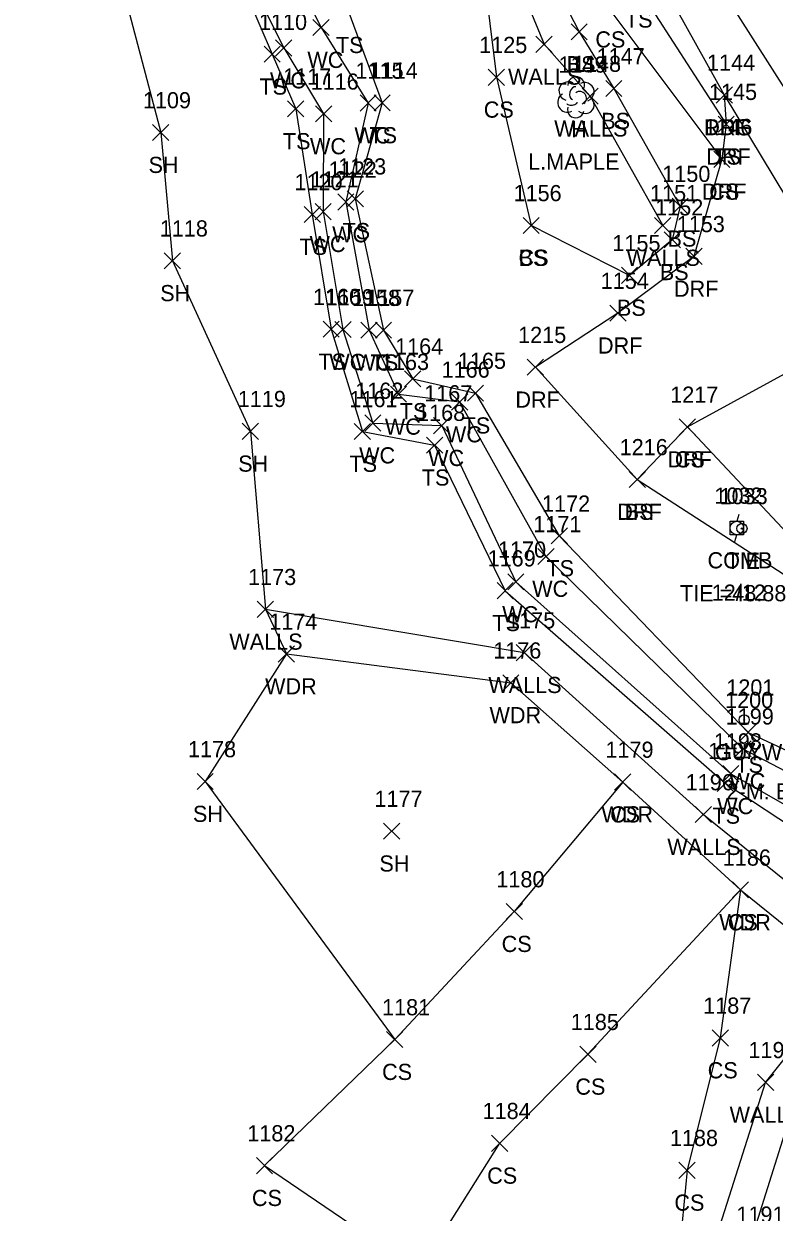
# Model space of a CAD drawing. Extents: x 1441651 to 1442140, y 243798 to 245625.
# Drawn here: x 1441906.3 to 1441999.2, y 245354.1 to 245501.1 of the extents above; entities that cross this region are included whole.
import ezdxf

# ---------------------------------------------------------------- set-up
doc = ezdxf.new("R2010")
doc.units = 0
for name, color, linetype in [('C_A', 7, 'Continuous'), ('C_C', 7, 'Continuous'), ('C_I', 7, 'Continuous'), ('CBP', 7, 'Continuous'), ('L_A', 7, 'Continuous'), ('L_C', 7, 'Continuous'), ('L_I', 7, 'Continuous'), ('L_TIC', 7, 'Continuous'), ('LAWA', 7, 'Continuous'), ('LAWE', 7, 'Continuous'), ('LELB', 7, 'Continuous'), ('LSOGP', 7, 'Continuous'), ('LTD', 7, 'Continuous'), ('LWS', 7, 'Continuous'), ('P_A', 7, 'Continuous'), ('P_I', 7, 'Continuous'), ('P_TIC', 7, 'Continuous'), ('PEU', 7, 'Continuous'), ('PRC', 7, 'Continuous'), ('R_A', 7, 'Continuous'), ('R_I', 7, 'Continuous'), ('R_TIC', 7, 'Continuous'), ('RDF', 7, 'Continuous'), ('U_A', 7, 'Continuous'), ('U_C', 7, 'Continuous'), ('U_I', 7, 'Continuous'), ('UP', 7, 'Continuous'), ('UPGW', 7, 'Continuous')]:
    doc.layers.add(name, color=color, linetype=linetype)

msp = doc.modelspace()

# ---------------------------------------------------------------- linework, layer by layer
at = {"layer": 'CBP'}
for radius in [0.625, 0.0833]:
    msp.add_circle((1441995.18, 245438.67), radius, dxfattribs=at)
at = {"layer": 'L_TIC'}
for points in [[(1441942.11, 245499.64), (1441944.11, 245501.64)], [(1441944.11, 245499.64), (1441942.11, 245501.64)], [(1441974.05, 245499.1), (1441976.05, 245501.1)], [(1441976.05, 245499.1), (1441974.05, 245501.1)], [(1441936.07, 245496.34), (1441938.07, 245498.34)], [(1441938.07, 245496.34), (1441936.07, 245498.34)], [(1441937.49, 245497.11), (1441939.49, 245499.11)], [(1441939.49, 245497.11), (1441937.49, 245499.11)], [(1441969.7, 245497.57), (1441971.7, 245499.57)], [(1441971.7, 245497.57), (1441969.7, 245499.57)], [(1441963.8, 245493.49), (1441965.8, 245495.49)], [(1441965.8, 245493.49), (1441963.8, 245495.49)], [(1441978.33, 245492.09), (1441980.33, 245494.09)], [(1441980.33, 245492.09), (1441978.33, 245494.09)], [(1441947.93, 245490.3), (1441949.93, 245492.3)], [(1441949.93, 245490.3), (1441947.93, 245492.3)], [(1441949.68, 245490.32), (1441951.68, 245492.32)], [(1441951.68, 245490.32), (1441949.68, 245492.32)], [(1441975.4, 245491.16), (1441977.4, 245493.16)], [(1441977.4, 245491.16), (1441975.4, 245493.16)], [(1441938.98, 245489.58), (1441940.98, 245491.58)], [(1441940.98, 245489.58), (1441938.98, 245491.58)], [(1441942.43, 245488.96), (1441944.43, 245490.96)], [(1441944.43, 245488.96), (1441942.43, 245490.96)], [(1441992.22, 245487.68), (1441994.22, 245489.68)], [(1441994.22, 245487.68), (1441992.22, 245489.68)], [(1441922.28, 245486.65), (1441924.28, 245488.65)], [(1441924.28, 245486.65), (1441922.28, 245488.65)], [(1441991.69, 245483.34), (1441993.69, 245485.34)], [(1441993.69, 245483.34), (1441991.69, 245485.34)], [(1441945.18, 245478.07), (1441947.18, 245480.07)], [(1441947.18, 245478.07), (1441945.18, 245480.07)], [(1441946.35, 245478.46), (1441948.35, 245480.46)], [(1441948.35, 245478.46), (1441946.35, 245480.46)], [(1441986.53, 245477.54), (1441988.53, 245479.54)], [(1441988.53, 245477.54), (1441986.53, 245479.54)], [(1441941.03, 245476.52), (1441943.03, 245478.52)], [(1441943.03, 245476.52), (1441941.03, 245478.52)], [(1441942.38, 245476.87), (1441944.38, 245478.87)], [(1441944.38, 245476.87), (1441942.38, 245478.87)], [(1441968.1, 245475.16), (1441970.1, 245477.16)], [(1441970.1, 245475.16), (1441968.1, 245477.16)], [(1441968.1, 245475.16), (1441970.1, 245477.16)], [(1441970.1, 245475.16), (1441968.1, 245477.16)], [(1441984.37, 245475.16), (1441986.37, 245477.16)], [(1441986.37, 245475.16), (1441984.37, 245477.16)], [(1441985.56, 245473.39), (1441987.56, 245475.39)], [(1441987.56, 245473.39), (1441985.56, 245475.39)], [(1441923.72, 245470.79), (1441925.72, 245472.79)], [(1441925.72, 245470.79), (1441923.72, 245472.79)], [(1441980.27, 245468.98), (1441982.27, 245470.98)], [(1441982.27, 245468.98), (1441980.27, 245470.98)], [(1441943.37, 245462.32), (1441945.37, 245464.32)], [(1441945.37, 245462.32), (1441943.37, 245464.32)], [(1441944.82, 245462.28), (1441946.82, 245464.28)], [(1441946.82, 245462.28), (1441944.82, 245464.28)], [(1441948.05, 245462.2), (1441950.05, 245464.2)], [(1441950.05, 245462.2), (1441948.05, 245464.2)], [(1441949.83, 245462.21), (1441951.83, 245464.21)], [(1441951.83, 245462.21), (1441949.83, 245464.21)], [(1441953.45, 245456.19), (1441955.45, 245458.19)], [(1441955.45, 245456.19), (1441953.45, 245458.19)], [(1441951.69, 245454.28), (1441953.69, 245456.28)], [(1441953.69, 245454.28), (1441951.69, 245456.28)], [(1441961.21, 245454.42), (1441963.21, 245456.42)], [(1441963.21, 245454.42), (1441961.21, 245456.42)], [(1441959.25, 245453.33), (1441961.25, 245455.33)], [(1441961.25, 245453.33), (1441959.25, 245455.33)], [(1441948.52, 245450.72), (1441950.52, 245452.72)], [(1441950.52, 245450.72), (1441948.52, 245452.72)], [(1441933.37, 245449.7), (1441935.37, 245451.7)], [(1441935.37, 245449.7), (1441933.37, 245451.7)], [(1441947.22, 245449.68), (1441949.22, 245451.68)], [(1441949.22, 245449.68), (1441947.22, 245451.68)], [(1441957.04, 245450.4), (1441959.04, 245452.4)], [(1441959.04, 245450.4), (1441957.04, 245452.4)], [(1441987.43, 245450.23), (1441989.43, 245452.23)], [(1441989.43, 245450.23), (1441987.43, 245452.23)], [(1441956.16, 245447.98), (1441958.16, 245449.98)], [(1441958.16, 245447.98), (1441956.16, 245449.98)], [(1441981.23, 245443.74), (1441983.23, 245445.74)], [(1441983.23, 245443.74), (1441981.23, 245445.74)], [(1441971.58, 245436.76), (1441973.58, 245438.76)], [(1441973.58, 245436.76), (1441971.58, 245438.76)], [(1441969.93, 245434.22), (1441971.93, 245436.22)], [(1441971.93, 245434.22), (1441969.93, 245436.22)], [(1441964.89, 245429.98), (1441966.89, 245431.98)], [(1441966.89, 245429.98), (1441964.89, 245431.98)], [(1441966.21, 245431.07), (1441968.21, 245433.07)], [(1441968.21, 245431.07), (1441966.21, 245433.07)], [(1441935.22, 245427.68), (1441937.22, 245429.68)], [(1441937.22, 245427.68), (1441935.22, 245429.68)], [(1441937.82, 245422.16), (1441939.82, 245424.16)], [(1441939.82, 245422.16), (1441937.82, 245424.16)], [(1441967.25, 245422.32), (1441969.25, 245424.32)], [(1441969.25, 245422.32), (1441967.25, 245424.32)], [(1441965.59, 245418.59), (1441967.59, 245420.59)], [(1441967.59, 245418.59), (1441965.59, 245420.59)], [(1441994.95, 245412.46), (1441996.95, 245414.46)], [(1441996.95, 245412.46), (1441994.95, 245414.46)], [(1441994.3, 245410.43), (1441996.3, 245412.43)], [(1441996.3, 245410.43), (1441994.3, 245412.43)], [(1441992.81, 245407.34), (1441994.81, 245409.34)], [(1441994.81, 245407.34), (1441992.81, 245409.34)], [(1441927.77, 245406.38), (1441929.77, 245408.38)], [(1441929.77, 245406.38), (1441927.77, 245408.38)], [(1441979.43, 245406.31), (1441981.43, 245408.31)], [(1441981.43, 245406.31), (1441979.43, 245408.31)], [(1441979.43, 245406.31), (1441981.43, 245408.31)], [(1441981.43, 245406.31), (1441979.43, 245408.31)], [(1441992.12, 245406.16), (1441994.12, 245408.16)], [(1441994.12, 245406.16), (1441992.12, 245408.16)], [(1441989.4, 245402.29), (1441991.4, 245404.29)], [(1441991.4, 245402.29), (1441989.4, 245404.29)], [(1441950.84, 245400.24), (1441952.84, 245402.24)], [(1441952.84, 245400.24), (1441950.84, 245402.24)], [(1441993.99, 245392.97), (1441995.99, 245394.97)], [(1441995.99, 245392.97), (1441993.99, 245394.97)], [(1441993.99, 245392.97), (1441995.99, 245394.97)], [(1441995.99, 245392.97), (1441993.99, 245394.97)], [(1441966.01, 245390.29), (1441968.01, 245392.29)], [(1441968.01, 245390.29), (1441966.01, 245392.29)], [(1441951.22, 245374.46), (1441953.22, 245376.46)], [(1441953.22, 245374.46), (1441951.22, 245376.46)], [(1441991.5, 245374.66), (1441993.5, 245376.66)], [(1441993.5, 245374.66), (1441991.5, 245376.66)], [(1441975.13, 245372.64), (1441977.13, 245374.64)], [(1441977.13, 245372.64), (1441975.13, 245374.64)], [(1441997.11, 245369.16), (1441999.11, 245371.16)], [(1441999.11, 245369.16), (1441997.11, 245371.16)], [(1441964.21, 245361.63), (1441966.21, 245363.63)], [(1441966.21, 245361.63), (1441964.21, 245363.63)], [(1441935.12, 245358.87), (1441937.12, 245360.87)], [(1441937.12, 245358.87), (1441935.12, 245360.87)], [(1441987.38, 245358.29), (1441989.38, 245360.29)], [(1441989.38, 245358.29), (1441987.38, 245360.29)]]:
    msp.add_lwpolyline(points, dxfattribs=at)
at = {"layer": 'LAWA'}
msp.add_lwpolyline([(1441938.82, 245423.16), (1441966.59, 245419.59), (1441980.43, 245407.31), (1441994.99, 245393.97), (1442005.69, 245385.38), (1442010.09, 245391.87), (1442016.01, 245382.46), (1442013.07, 245379.25), (1442007.39, 245367.36), (1442001.16, 245351.18), (1441996.64, 245344.41), (1441988.52, 245326.61)], dxfattribs=at)
at = {"layer": 'LAWE'}
for points in [[(1441907.7, 245568.2), (1441910.35, 245545.1), (1441926.4, 245522.2), (1441938.49, 245498.11), (1441943.43, 245489.96), (1441943.38, 245477.87), (1441945.82, 245463.28), (1441949.52, 245451.72), (1441958.04, 245451.4), (1441967.21, 245432.07), (1441993.81, 245408.34), (1442004, 245402.53), (1442022.03, 245379.96)], [(1441911.34, 245568.34), (1441913.54, 245547.37), (1441930.79, 245525.13), (1441943.11, 245500.64), (1441948.93, 245491.3), (1441946.18, 245479.07), (1441949.05, 245463.2), (1441952.69, 245455.28), (1441960.25, 245454.33), (1441970.93, 245435.22), (1441995.3, 245411.43), (1442005.92, 245405.86), (1442024.36, 245389.77), (1442033, 245390.02)]]:
    msp.add_lwpolyline(points, dxfattribs=at)
at = {"layer": 'LELB'}
for points in [[(1441933.72, 245589.33), (1441948.49, 245558.46), (1441956.21, 245536.7), (1441975.05, 245500.1), (1441979.33, 245493.09), (1441987.53, 245478.54), (1441986.56, 245474.39), (1441981.27, 245469.98), (1441969.1, 245476.16)], [(1441935.55, 245590.25), (1441950.41, 245561.12), (1441965.85, 245535.51), (1441982.29, 245505.63), (1441993.22, 245488.68)], [(1441923.45, 245583.22), (1441912.77, 245568.1), (1441914.39, 245547.71), (1441930.79, 245525.13), (1441946.54, 245502.48), (1441950.68, 245491.32), (1441947.35, 245479.46), (1441950.83, 245463.21), (1441954.45, 245457.19), (1441962.21, 245455.42), (1441972.58, 245437.76), (1441995.95, 245413.46), (1442007.46, 245408.08), (1442021.35, 245397.08), (1442029.3, 245403.17), (1442035.63, 245410.33), (1442039.93, 245412.91), (1442042.78, 245414.27)], [(1441906.34, 245567.87), (1441908.84, 245544.58), (1441926.4, 245522.2), (1441937.07, 245497.34), (1441939.98, 245490.58), (1441942.03, 245477.52), (1441944.37, 245463.32), (1441948.22, 245450.68), (1441957.16, 245448.98), (1441965.89, 245430.98), (1441993.12, 245407.16), (1442003.12, 245400.59), (1442010.09, 245391.87)], [(1441965.85, 245535.51), (1441978.6, 245503.17), (1441992.69, 245484.34)], [(1441961.57, 245520.77), (1441964.8, 245494.49), (1441969.1, 245476.16)], [(1441988.43, 245451.23), (1442003.87, 245434.81), (1442025.23, 245431.01), (1442028.78, 245424.28), (1442035.63, 245410.33)], [(1441982.23, 245444.74), (1442002.27, 245431.8), (1442015.27, 245424.48), (1442035.63, 245410.33)], [(1441980.43, 245407.31), (1441967.01, 245391.29), (1441952.22, 245375.46), (1441936.12, 245359.87)], [(1441955.27, 245346.86), (1441965.21, 245362.63), (1441976.13, 245373.64), (1441994.99, 245393.97), (1441992.5, 245375.66), (1441988.38, 245359.29), (1441985.51, 245329.27), (1441996.05, 245349.81), (1442001.58, 245367.37), (1442003.86, 245377.37), (1442005.69, 245385.38), (1442010.09, 245391.87)]]:
    msp.add_lwpolyline(points, dxfattribs=at)
at = {"layer": 'LSOGP'}
msp.add_lwpolyline([(1441916.15, 245514.72), (1441923.28, 245487.65), (1441924.72, 245471.79), (1441934.37, 245450.7), (1441936.22, 245428.68), (1441938.82, 245423.16), (1441928.77, 245407.38), (1441952.22, 245375.46), (1441936.12, 245359.87), (1441955.27, 245346.86)], dxfattribs=at)
at = {"layer": 'LTD'}
msp.add_line((1441974.62, 245492.06), (1441974.62, 245492.06), dxfattribs=at)
msp.add_line((1441974.62, 245492.06), (1441974.62, 245492.06), dxfattribs=at)
msp.add_arc((1441974.67, 245493.5), 1.05, 335.5272, 180.9563, dxfattribs=at)
for centre, major_axis, ratio, start_param, end_param in [((1441973.83, 245492.73), (1.21, -0.51), 0.895232, 1.570796, 4.712389), ((1441975.66, 245492.65), (-1.14, -0.48), 0.949671, 1.570796, 4.712389), ((1441973.54, 245491.35), (0.58, -1.04), 0.959034, 3.141593, 6.283185), ((1441974.41, 245492.52), (-0.208, -0.792), 0.645439, 3.141593, 6.283185), ((1441975.12, 245491.9), (-0.5, 0.667), 0.989748, 3.141593, 6.283185), ((1441974.62, 245490.56), (0.26, 1.06), 0.942809, 1.570796, 4.712389), ((1441974.16, 245491.31), (-0.625, -0.083), 0.423636, 0, 3.141593), ((1441975.62, 245491.23), (-1.09, 0.79), 0.841452, 1.570796, 4.712389)]:
    msp.add_ellipse(centre, major_axis=major_axis, ratio=ratio, start_param=start_param, end_param=end_param, dxfattribs=at)
at = {"layer": 'LWS'}
for points in [[(1441954.96, 245536.46), (1441961.57, 245520.77), (1441970.7, 245498.57), (1441976.4, 245492.16), (1441985.37, 245476.16)], [(1441936.22, 245428.68), (1441968.25, 245423.32), (1441990.4, 245403.29), (1442004.47, 245391.95)], [(1441985.51, 245329.27), (1441991.35, 245348.99), (1441998.11, 245370.16), (1442003.86, 245377.37), (1442013.07, 245379.25)]]:
    msp.add_lwpolyline(points, dxfattribs=at)
at = {"layer": 'P_TIC'}
for points in [[(1441991.99, 245491.3), (1441993.99, 245493.3)], [(1441993.99, 245491.3), (1441991.99, 245493.3)]]:
    msp.add_lwpolyline(points, dxfattribs=at)
at = {"layer": 'PEU'}
msp.add_lwpolyline([(1441937.94, 245591.88), (1441953.89, 245562.72), (1441968.91, 245535.69), (1441984.8, 245506.98), (1441992.99, 245492.3), (1442013.08, 245458.97), (1442024.73, 245444.52), (1442043.13, 245414.63), (1442048.27, 245419.3), (1442053.64, 245424.38)], dxfattribs=at)
at = {"layer": 'PRC'}
msp.add_lwpolyline([(1441943.37, 245595.22), (1441959.06, 245565.31), (1441973.71, 245538.05), (1441989.92, 245509.63), (1442005.51, 245485.14), (1442020.38, 245462.65), (1442040.92, 245430.94), (1442048.27, 245419.3)], dxfattribs=at)
at = {"layer": 'R_TIC'}
for points in [[(1441991.99, 245491.3), (1441993.99, 245493.3)], [(1441993.99, 245491.3), (1441991.99, 245493.3)], [(1441992.22, 245487.68), (1441994.22, 245489.68)], [(1441994.22, 245487.68), (1441992.22, 245489.68)], [(1441991.69, 245483.34), (1441993.69, 245485.34)], [(1441993.69, 245483.34), (1441991.69, 245485.34)], [(1441988.24, 245471.33), (1441990.24, 245473.33)], [(1441990.24, 245471.33), (1441988.24, 245473.33)], [(1441978.84, 245464.31), (1441980.84, 245466.31)], [(1441980.84, 245464.31), (1441978.84, 245466.31)], [(1441968.62, 245457.62), (1441970.62, 245459.62)], [(1441970.62, 245457.62), (1441968.62, 245459.62)], [(1441987.43, 245450.23), (1441989.43, 245452.23)], [(1441989.43, 245450.23), (1441987.43, 245452.23)], [(1441981.23, 245443.74), (1441983.23, 245445.74)], [(1441983.23, 245443.74), (1441981.23, 245445.74)]]:
    msp.add_lwpolyline(points, dxfattribs=at)
at = {"layer": 'RDF'}
msp.add_lwpolyline([(1441992.99, 245492.3), (1441993.22, 245488.68), (1441992.69, 245484.34), (1441989.24, 245472.33), (1441979.84, 245465.31), (1441969.62, 245458.62), (1441982.23, 245444.74), (1441988.43, 245451.23), (1442004.08, 245459.77), (1442010.28, 245460.76), (1442013.08, 245458.97)], dxfattribs=at)
at = {"layer": 'UP'}
for p, q in [((1441993.71, 245437.91), (1441993.71, 245439.58)), ((1441993.71, 245439.58), (1441995.37, 245439.58)), ((1441994.79, 245440.41), (1441994.54, 245439.58)), ((1441995.37, 245439.58), (1441995.37, 245437.91)), ((1441995.37, 245437.91), (1441993.71, 245437.91)), ((1441994.29, 245437.08), (1441994.54, 245437.91)), ((1441994.54, 245438.74), (1441994.54, 245438.74))]:
    msp.add_line(p, q, dxfattribs=at)
msp.add_circle((1441994.54, 245438.74), 0.833, dxfattribs=at)
at = {"layer": 'UPGW'}
for radius in [0.625, 0.0833]:
    msp.add_circle((1441995.45, 245415.01), radius, dxfattribs=at)

# ---------------------------------------------------------------- texts
at = {"layer": 'C_A'}
msp.add_text('TIE', height=2, dxfattribs=at).set_placement((1441993.26, 245433.67))
at = {"layer": 'C_C'}
msp.add_text('TIE =48.88', height=2, dxfattribs=at).set_placement((1441987.51, 245429.67))
at = {"layer": 'C_I'}
msp.add_text('1033', height=2, dxfattribs=at).set_placement((1441992.41, 245441.67))
at = {"layer": 'L_A'}
for s, p in [('TS', (1441980.7, 245500.63)), ('CS', (1441977.04, 245498.17)), ('TS', (1441944.95, 245497.48)), ('WC', (1441941.42, 245495.64)), ('BS', (1441973.5, 245495.1)), ('WALLS', (1441966.24, 245493.57)), ('TS', (1441935.48, 245492.34)), ('WC', (1441936.79, 245493.11)), ('CS', (1441963.24, 245489.49)), ('BS', (1441977.77, 245488.09)), ('WC', (1441947.24, 245486.3)), ('TS', (1441949.09, 245486.32)), ('WALLS', (1441971.95, 245487.16)), ('H', (1441974.05, 245487.06)), ('TS', (1441938.39, 245485.58)), ('WC', (1441941.74, 245484.96)), ('TS', (1441991.63, 245483.68)), ('SH', (1441921.77, 245482.65)), ('CS', (1441991.13, 245479.34)), ('WC', (1441944.48, 245474.07)), ('TS', (1441945.76, 245474.46)), ('WC', (1441941.69, 245472.87)), ('BS', (1441985.97, 245473.54)), ('TS', (1441940.44, 245472.52)), ('CS', (1441967.54, 245471.16)), ('BS', (1441967.54, 245471.16)), ('WALLS', (1441980.91, 245471.16)), ('BS', (1441985.01, 245469.39)), ('SH', (1441923.21, 245466.79)), ('BS', (1441979.71, 245464.98)), ('TS', (1441942.78, 245458.32)), ('WC', (1441944.13, 245458.28)), ('WC', (1441947.36, 245458.2)), ('TS', (1441949.24, 245458.21)), ('TS', (1441952.85, 245452.19)), ('WC', (1441951, 245450.28)), ('WC', (1441958.56, 245449.33)), ('TS', (1441960.62, 245450.42)), ('WC', (1441947.82, 245446.72)), ('WC', (1441956.35, 245446.4)), ('CS', (1441986.87, 245446.23)), ('SH', (1441932.86, 245445.7)), ('TS', (1441946.63, 245445.68)), ('TS', (1441955.57, 245443.98)), ('BS', (1441980.67, 245439.74)), ('TS', (1441970.99, 245432.76)), ('WC', (1441969.23, 245430.22)), ('WC', (1441965.52, 245427.07)), ('TS', (1441964.3, 245425.98)), ('WALLS', (1441931.76, 245423.68)), ('WALLS', (1441963.8, 245418.32)), ('WDR', (1441936.19, 245418.16)), ('WDR', (1441963.95, 245414.59)), ('TS', (1441994.36, 245408.46)), ('WC', (1441993.61, 245406.43)), ('SH', (1441927.26, 245402.38)), ('WDR', (1441977.79, 245402.31)), ('CS', (1441978.87, 245402.31)), ('TS', (1441991.53, 245402.16)), ('WC', (1441992.12, 245403.34)), ('WALLS', (1441985.95, 245398.29)), ('SH', (1441950.33, 245396.24)), ('WDR', (1441992.36, 245388.97)), ('CS', (1441993.43, 245388.97)), ('CS', (1441965.45, 245386.29)), ('CS', (1441950.66, 245370.46)), ('CS', (1441990.94, 245370.66)), ('CS', (1441974.57, 245368.64)), ('WALLS', (1441993.65, 245365.16)), ('CS', (1441963.66, 245357.63)), ('CS', (1441934.56, 245354.87)), ('CS', (1441986.82, 245354.29))]:
    msp.add_text(s, height=2, dxfattribs=at).set_placement(p)
at = {"layer": 'L_C'}
for s, p in [('L.MAPLE', (1441968.73, 245483.06)), ('2-M. BASSWOOD', (1441993.27, 245405.17))]:
    msp.add_text(s, height=2, dxfattribs=at).set_placement(p)
at = {"layer": 'L_I'}
for s, p in [('1110', (1441935.43, 245500.34)), ('1125', (1441962.67, 245497.49)), ('1149', (1441972.48, 245495.06)), ('1148', (1441974.28, 245495.16)), ('1147', (1441977.2, 245496.09)), ('1117', (1441938.42, 245493.58)), ('1115', (1441947.37, 245494.3)), ('1114', (1441949.12, 245494.32)), ('1116', (1441941.82, 245492.96)), ('1109', (1441921.07, 245490.65)), ('1145', (1441991.1, 245491.68)), ('1146', (1441990.51, 245487.34)), ('1122', (1441944.05, 245482.07)), ('1123', (1441945.22, 245482.46)), ('1150', (1441985.32, 245481.54)), ('1120', (1441939.82, 245480.52)), ('1121', (1441941.82, 245480.87)), ('1156', (1441966.92, 245479.16)), ('1156', (1441966.92, 245479.16)), ('1151', (1441983.81, 245479.16)), ('1152', (1441984.44, 245477.39)), ('1118', (1441923.16, 245474.79)), ('1155', (1441979.15, 245472.98)), ('1160', (1441942.11, 245466.32)), ('1159', (1441943.69, 245466.28)), ('1158', (1441946.93, 245466.2)), ('1157', (1441948.7, 245466.21)), ('1164', (1441952.27, 245460.19)), ('1163', (1441950.52, 245458.28)), ('1165', (1441960.04, 245458.42)), ('1166', (1441958.02, 245457.33)), ('1119', (1441932.81, 245453.7)), ('1161', (1441946.62, 245453.68)), ('1162', (1441947.34, 245454.72)), ('1167', (1441955.87, 245454.4)), ('1217', (1441986.3, 245454.23)), ('1168', (1441954.99, 245451.98)), ('1216', (1441980.05, 245447.74)), ('1172', (1441970.45, 245440.76)), ('1171', (1441969.37, 245438.22)), ('1170', (1441965, 245435.07)), ('1169', (1441963.71, 245433.98)), ('1173', (1441934.09, 245431.68)), ('1174', (1441936.7, 245426.16)), ('1175', (1441966.13, 245426.32)), ('1176', (1441964.41, 245422.59)), ('1200', (1441993.09, 245416.46)), ('1199', (1441993.17, 245414.43)), ('1198', (1441991.69, 245411.34)), ('1178', (1441926.65, 245410.38)), ('1179', (1441978.29, 245410.31)), ('1179', (1441978.29, 245410.31)), ('1197', (1441990.99, 245410.16)), ('1196', (1441988.22, 245406.29)), ('1177', (1441949.72, 245404.24)), ('1186', (1441992.81, 245396.97)), ('1186', (1441992.81, 245396.97)), ('1180', (1441964.8, 245394.29)), ('1187', (1441990.38, 245378.66)), ('1181', (1441950.66, 245378.46)), ('1185', (1441974, 245376.64)), ('1193', (1441995.98, 245373.16)), ('1184', (1441963.09, 245365.63)), ('1182', (1441933.99, 245362.87)), ('1188', (1441986.26, 245362.29)), ('1191', (1441994.49, 245352.81))]:
    msp.add_text(s, height=2, dxfattribs=at).set_placement(p)
at = {"layer": 'P_A'}
msp.add_text('RDG', height=2, dxfattribs=at).set_placement((1441990.48, 245487.3))
at = {"layer": 'P_I'}
msp.add_text('1144', height=2, dxfattribs=at).set_placement((1441990.86, 245495.3))
at = {"layer": 'R_A'}
for p in [(1441990.52, 245487.3), (1441990.76, 245483.68), (1441990.23, 245479.34), (1441986.77, 245467.33), (1441977.37, 245460.31), (1441967.15, 245453.62), (1441985.96, 245446.23), (1441979.76, 245439.74)]:
    msp.add_text('DRF', height=2, dxfattribs=at).set_placement(p)
at = {"layer": 'R_I'}
for s, p in [('1144', (1441990.86, 245495.3)), ('1145', (1441991.1, 245491.68)), ('1146', (1441990.51, 245487.34)), ('1153', (1441987.11, 245475.33)), ('1154', (1441977.71, 245468.31)), ('1215', (1441967.49, 245461.62)), ('1217', (1441986.3, 245454.23)), ('1216', (1441980.05, 245447.74))]:
    msp.add_text(s, height=2, dxfattribs=at).set_placement(p)
at = {"layer": 'U_A'}
for s, p in [('COMB', (1441990.92, 245433.74)), ('GUYW', (1441991.84, 245410.01))]:
    msp.add_text(s, height=2, dxfattribs=at).set_placement(p)
at = {"layer": 'U_C'}
msp.add_text('12/12', height=2, dxfattribs=at).set_placement((1441991.44, 245429.74))
at = {"layer": 'U_I'}
for s, p in [('1032', (1441991.77, 245441.74)), ('1201', (1441993.24, 245418.01))]:
    msp.add_text(s, height=2, dxfattribs=at).set_placement(p)

doc.saveas('drawing.dxf')
